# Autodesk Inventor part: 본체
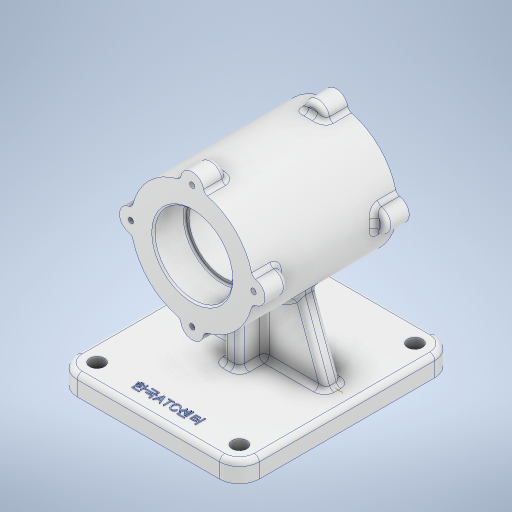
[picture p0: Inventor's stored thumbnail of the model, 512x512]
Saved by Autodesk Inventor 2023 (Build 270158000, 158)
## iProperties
Created: 2023-08
Part Number: 본체
Material: 알루미늄 6061
Document SubType Name: Modeling
Designer: asung
Density: 2.7 g/cm^3
Appearance: 알루미늄 - 평지
Mass: 1218.04 g
Surface Area: 798.427 cm^2
Volume: 451.126 cm^3
Author: asung
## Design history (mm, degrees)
sketch "스케치1"
  geometry: L1 (43, -65)-(-43, -65); L2 (-55, -53)-(-55, 53); L3 (-43, 65)-(43, 65); L4 (55, 53)-(55, -53); L5 (55, -65)-(-55, 65); L6 (-55, -65)-(55, 65); C1 r 4.5 at (43, 53); C2 r 4.5 at (43, -53); C3 r 4.5 at (-43, -53); C4 r 4.5 at (-43, 53); A1 r 12 centre (43, 53) between (55, 53) and (43, 65); A2 r 12 centre (43, -53) between (43, -65) and (55, -53); A3 r 12 centre (-43, -53) between (-55, -53) and (-43, -65); A4 r 12 centre (-43, 53) between (-43, 65) and (-55, 53); 1 further point
  constraints: 12 end point, 8 centre point, 8 point on circle, 8 point on line, 8 tangent, 4 coincident, 3 equal radius, 2 midpoint, 2 parallel, 1 horizontal, 1 perpendicular
  dimensions: "d0" = 110 distance of L5.end L6.end; "d1" = 130 distance of L6.start L5.end; "d2" = 12 radius of A1; "d3" = 9 diameter of C1; "d4" = 9 diameter of C2; "d5" = 9 diameter of C3; "d6" = 9 diameter of C4
extrude "돌출1" new body sketch "스케치1" distance "d7" = 12; taper "d8" = 0 deg
node "작업 평면1"
sketch "스케치2"
  geometry: L1 (43, 0)-(43, 82); C1 r 37 at (43, 82)
  constraints: 2 end point, 1 centre point, 1 coincident, 1 vertical
  dimensions: "d10" = 82 distance of L1.start L1.end; "d11" = 74 diameter of C1
extrude "돌출2" join sketch "스케치2" stored distance "d12" = 87; taper "d13" = 0 deg
sketch "스케치3"
  geometry: C1 r 37 at (0, 0) reference; 2 further points
  constraints: 1 coincident
hole "구멍1" sketch "스케치3" at (0, 0) diameter "d14" = 42; stored, may be unused: countersink angle "d18" = 82 deg, drill point angle "d20" = 0 deg; dims "d15" = 8, "d16" = 47, "d17" = 19, "d19" = 87
sketch "스케치4"
  geometry: C1 r 37 at (0, 0) reference; 2 further points
  constraints: 1 coincident
hole "구멍2" sketch "스케치4" at (0, 0) diameter "d21" = 42; stored, may be unused: countersink angle "d25" = 90 deg, drill point angle "d27" = 0 deg; dims "d22" = 6, "d23" = 47, "d24" = 19, "d26" = 87
chamfer "모따기1" distance "d28" = 1; stored, may be unused: second distance "d29" = 2, angle "d30" = 45 deg
sketch "스케치5"
  geometry: 1 further point
sketch "스케치6"
  geometry: C1 r 37 at (0, 0) reference; C2 r 7 at (0, 37); 2 further points
  constraints: 1 centre point, 1 vertical alignment, 1 other
  dimensions: "d31" = 14 diameter of C2
extrude "돌출3" join sketch "스케치6" distance "d32" = 14; taper "d33" = 0 deg
fillet "모깎기1" dims "d34" = 3
fillet "모깎기2" dims "d35" = 3
sketch "스케치7"
  geometry: A1 r 7 centre (43, 119) between (49.889, 120.239) and (36.111, 120.239) reference; 2 further points
  constraints: 1 coincident
hole "구멍3" sketch "스케치7" at (43, 119) diameter "d36" = 3.242; stored, may be unused: countersink angle "d40" = 90 deg, drill point angle "d42" = 118 deg; dims "d37" = 8, "d38" = 47, "d39" = 19, "d41" = 10
node "작업 평면2"
sketch "스케치8"
  geometry: L1 (-43, -65)-(43, -65) reference; L2 (0, -65)-(0, 5); L3 (5, -15)-(-5, -15); L4 (-5, -15)-(-5, 25); L5 (-5, 25)-(5, 25); L6 (5, 25)-(5, -15); L7 (5, -15)-(-5, 25); L8 (-5, -15)-(5, 25); 1 further point
  constraints: 14 end point, 3 midpoint, 2 parallel, 1 horizontal, 1 perpendicular, 1 vertical
  dimensions: "d46" = 70 distance of L2.start L2.end; "d47" = 10 distance of L4.end L5.end; "d48" = 40 distance of L3.end L4.end
extrude "돌출4" join sketch "스케치8" stored distance "d49" = 14; taper "d50" = 0 deg
node "작업 평면3"
sketch "스케치10"
  geometry: L1 (-12, 0)-(-12, 12) reference; L2 (16.837, 55.837)-(0.882, 12); L3 (0, 12)-(-12, 12) reference; L4 (69.163, 55.837)-(85.118, 12); A1 r 37 centre (43, 82) between (7.138, 72.896) and (33.896, 46.138) reference; 1 further point
  constraints: 4 end point, 1 point on circle, 1 point on line
  dimensions: "d64" = 110 deg angle of L3 L2
feature "리브2" dims "d65" = 1, "d66" = 10, "d67" = 0, "d68" = 0, "d69" = 1, "d70" = 1
feature "리브3" dims "d71" = 1, "d72" = 10, "d73" = 0, "d74" = 0, "d75" = 1, "d76" = 1
sketch "스케치11"
  geometry: 1 further point
fillet "모깎기3" dims "d77" = 3
fillet "모깎기4" dims "d78" = 3
fillet "모깎기5" dims "d79" = 3
fillet "모깎기6" dims "d80" = 3
sketch "스케치12"
  geometry: L1 (-52, 53)-(-52, -53) reference; L2 (-43, -62)-(43, -62) reference; L3 (52, -53)-(52, 53) reference; L4 (43, 62)-(-43, 62) reference; L5 (37.834, 13)-(8, 13) reference; L6 (8, 13)-(8, 22) reference; L7 (2, 28)-(-2, 28) reference; L8 (-8, 22)-(-8, 13) reference; L9 (-8, 13)-(-37.834, 13) reference; L10 (-44.219, 7)-(-44.219, 3) reference; L11 (-37.834, -3)-(-8, -3) reference; L12 (-8, -3)-(-8, -12) reference; L13 (-2, -18)-(2, -18) reference; L14 (8, -12)-(8, -3) reference; L15 (8, -3)-(37.834, -3) reference; L16 (44.219, 3)-(44.219, 7) reference; L17 (77, 5)-(-77, 5) reference; L18 (-55, 53)-(-55, -53) reference; C1 r 4.5 at (-43, -53) reference; C2 r 4.5 at (-43, 53) reference; C3 r 4.5 at (43, 53) reference; C4 r 4.5 at (43, -53) reference; A1 r 9 centre (-43, 53) between (-43, 62) and (-52, 53) reference; A2 r 9 centre (-43, -53) between (-52, -53) and (-43, -62) reference; A3 r 9 centre (43, -53) between (43, -62) and (52, -53) reference; A4 r 9 centre (43, 53) between (52, 53) and (43, 62) reference; A5 r 6 centre (2, 22) between (8, 22) and (2, 28) reference; A6 r 6 centre (-2, 22) between (-2, 28) and (-8, 22) reference; A7 r 6 centre (-2, -12) between (-8, -12) and (-2, -18) reference; A8 r 6 centre (2, -12) between (2, -18) and (8, -12) reference; 2 further points
  constraints: 5 other
  dimensions: "d81" = 58 distance from line of point (0, -53) L17; "d83" = 55 distance from line of L18 point (0, -53)
  node "절단 모서리 투영1"
sketch "스케치13"
  geometry: 1 further point
sketch "스케치14"
  geometry: 1 further point
node "작업 평면4"
sketch "스케치15"
  geometry: 1 further point
sketch "스케치16"
  geometry: 1 further point
feature "엠보싱1" dims "d84" = 0.5, "d85" = 0
fillet "모깎기7" dims "d86" = 1
feature "˻耀˽耀˿耀́耀̃耀̅耀̇耀̉耀" dims "d0" = 110, "d1" = 130, "d2" = 12, "d3" = 9, "d4" = 9, "d5" = 9, "d6" = 9, "d7" = 12, "d8" = 0, "d9" = -70, "d10" = 82, "d11" = 74, "d12" = 87, "d13" = 0, "d14" = 42, "d15" = 8, "d16" = 47, "d17" = 19, "d18" = 82 deg, "d19" = 87, "d20" = 0, "d21" = 42, "d22" = 6, "d23" = 47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
node "솔리드1"
pattern_circular "원형 패턴1" dims "d44" = 360 deg
mirror "미러1"
feature "A9D066F2-1C7D-4E18-AEED-F7BC21143FA4" dims "d14" = 42, "d15" = 8, "d16" = 47, "d17" = 19, "d18" = 82 deg, "d19" = 87, "d20" = 0
